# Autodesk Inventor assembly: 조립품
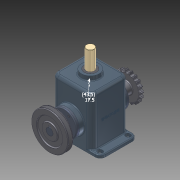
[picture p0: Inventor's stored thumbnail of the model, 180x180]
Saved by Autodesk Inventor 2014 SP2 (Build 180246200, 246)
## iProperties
Created: 2015-03
Part Number: 조립품
Document SubType Name: Assembly
Designer: 201-01
Author: 201-01
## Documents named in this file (15)
- C:\Users\201-01\Desktop\350305V1002\조립품.iam
- C:\Users\201-01\Desktop\350305V1002\본체.ipt
- C:\Users\201-01\Desktop\350305V1002\편심축.ipt
- C:\Users\201-01\Desktop\350305V1002\V-벨트풀리.ipt
- C:\Users\201-01\Desktop\350305V1002\체인 스프로킷.ipt
- C:\Users\201-01\Desktop\350305V1002\커버.ipt
- C:\Users\201-01\Desktop\350305V1002\슬라이드.ipt
- C:\Users\201-01\Desktop\350305V1002\가변스프링.ipt
- C:\Users\201-01\Desktop\350305V1002\베어링 6205.ipt
- C:\Users\201-01\Desktop\350305V1002\오일실.ipt
- C:\Users\201-01\Desktop\350305V1002\부시.ipt
- C:\Users\201-01\Desktop\350305V1002\키 8x8.ipt
- C:\Users\201-01\Desktop\350305V1002\멈춤링.ipt
- C:\Users\201-01\Desktop\350305V1002\M4x0.5.ipt
- C:\Users\201-01\Desktop\350305V1002\멈춤나사 M5x0.5.ipt
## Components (9 placed, 4 different names)
1. V-벨트풀리:1 — 각도:1, 플러쉬:1, 구동부
2. 5-체인 스프로킷:1 — 각도:2, 플러쉬:2
3. 가변스프링:1
4. M4x0.5:1 — 각도:5
5. M4x0.5:2
6. M4x0.5:3
7. M4x0.5:4 — 각도:6
8. M4x0.5:5
9. M4x0.5:6
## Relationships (7: Angle 5, Flush 2)
- 각도:1 [Angle]: V-벨트풀리:1
- 플러쉬:1 [Flush]: V-벨트풀리:1
- 각도:2 [Angle]: 5-체인 스프로킷:1
- 플러쉬:2 [Flush]: 5-체인 스프로킷:1
- 각도:5 [Angle]: M4x0.5:1
- 각도:6 [Angle]: M4x0.5:4
- 구동부 [Angle]: V-벨트풀리:1
